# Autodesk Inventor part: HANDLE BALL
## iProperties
Created: 2006-07
Part Number: HANDLE BALL
Material: Steel
Document SubType Name: Modeling
Designer: rollin42
Density: 7.85 g/cm^3
Author: rollin42
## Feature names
1. Revolution1
2. Extrusion1
3. Hole1
